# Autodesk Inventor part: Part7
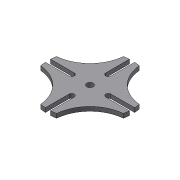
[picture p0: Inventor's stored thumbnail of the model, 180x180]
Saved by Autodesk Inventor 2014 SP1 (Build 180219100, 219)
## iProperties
Created: 2014-01
Part Number: Part7
Material: 一般
Document SubType Name: Modeling
Designer: Hashimoto
Density: 1 g/cm^3
Appearance: 既定
Mass: 184 g
Surface Area: 482.544 cm^2
Volume: 184 cm^3
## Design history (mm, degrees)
sketch "スケッチ3"
  geometry: L1 (6.35, 101.401)-(6.35, 44.251); L2 (-6.35, 44.251)-(-6.35, 101.401); L3 (-101.401, 6.35)-(-44.251, 6.35); L4 (-44.251, -6.35)-(-101.401, -6.35); L5 (-6.35, -101.401)-(-6.35, -44.251); L6 (6.35, -44.251)-(6.35, -101.401); L7 (101.401, -6.35)-(44.251, -6.35); L8 (44.251, 6.35)-(101.401, 6.35); C1 r 7.938 at (0, 0); A1 r 101.6 centre (0, 0) between (101.401, 6.35) and (99.765, 19.224); A2 r 88.9 centre (107.763, 107.763) between (19.224, 99.765) and (99.765, 19.224); A3 r 101.6 centre (0, 0) between (19.224, 99.765) and (6.35, 101.401); A4 r 6.35 centre (0, 44.251) between (-6.35, 44.251) and (6.35, 44.251); A5 r 101.6 centre (0, 0) between (-6.35, 101.401) and (-19.224, 99.765); A6 r 88.9 centre (-107.763, 107.763) between (-99.765, 19.224) and (-19.224, 99.765); A7 r 101.6 centre (0, 0) between (-99.765, 19.224) and (-101.401, 6.35); A8 r 6.35 centre (-44.251, 0) between (-44.251, -6.35) and (-44.251, 6.35); A9 r 101.6 centre (0, 0) between (-101.401, -6.35) and (-99.765, -19.224); A10 r 88.9 centre (-107.763, -107.763) between (-19.224, -99.765) and (-99.765, -19.224); A11 r 101.6 centre (0, 0) between (-19.224, -99.765) and (-6.35, -101.401); A12 r 6.35 centre (0, -44.251) between (6.35, -44.251) and (-6.35, -44.251); A13 r 101.6 centre (0, 0) between (6.35, -101.401) and (19.224, -99.765); A14 r 88.9 centre (107.763, -107.763) between (99.765, -19.224) and (19.224, -99.765); A15 r 101.6 centre (0, 0) between (99.765, -19.224) and (101.401, -6.35); A16 r 6.35 centre (44.251, 0) between (44.251, 6.35) and (44.251, -6.35); 1 further point
  constraints: 32 point on circle, 17 centre point, 16 end point
extrude "押し出し3" new body sketch "スケッチ3" distance "d6" = 10; taper "d7" = 0 deg
sketch "スケッチ4"
  geometry: C1 r 7.937 at (0, 0) reference; C2 r 20 at (0, 0)
  constraints: 1 centre point
  dimensions: "d8" = 40 diameter of C2
extrude "押し出し4" join sketch "スケッチ4" distance "d9" = 11; taper "d10" = 0 deg
node "ソリッド3"
